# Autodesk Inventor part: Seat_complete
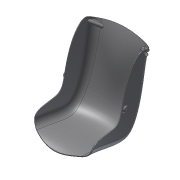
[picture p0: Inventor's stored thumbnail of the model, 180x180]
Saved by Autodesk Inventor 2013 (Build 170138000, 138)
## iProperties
Shininess: 64.0
Length Units: 11269
Angle Units: 11279
Time Units: 11290
Mass Units: 11283
Length Display Precision: 3
Angle Display Precision: 2
Compacted: True
Part Number: Seat_complete
Document SubType Name: Modeling
Created: 2002-10
Designer: FranzK
Density: 1 g/cm^3
Material: Generic
Density: 0.0
Volumn: 0.0
Area: 0.0
PropertySet Name: Model Information
Control State: 0
Master: False
Checked Out: False
Author: FranzK
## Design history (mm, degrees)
sketch "Sketch1"
  geometry: L1 (0, 40)-(0, 422.426) reference; L2 (0, 40)-(-230, 40); L3 (-230, 40)-(-230, 420); L4 (-230, 420)-(0, 420) reference; L5 (230, 40)-(230, 420); L6 (0, 40)-(230, 40); L7 (230, 420)-(0, 420)
  constraints: 14 end point, 2 symmetric about line, 2 vertical, 1 horizontal, 1 parallel, 1 perpendicular, 1 point on line, 3 other
  dimensions: "d0" = 460 diameter of L2.end L1; "d1" = 380 distance between parallel lines of L2 L4; "d2" = 90 deg angle of L2 L3
extrude "Extrusion1" new body sketch "Sketch1" distance "d3" = 600; taper "d4" = 0 deg
workplane "Work Plane2"
workplane "Work Plane3"
sketch "Sketch11"
  geometry: L1 (0, 380)-(-600, 380) reference; L2 (-600, 380)-(-600, 552.047); L3 (-600, 552.047)-(0, 380)
  constraints: 4 end point, 1 perpendicular
  dimensions: "d79" = 16 deg angle of L1 L3
extrude "Extrusion3" cut sketch "Sketch11" stored distance "d8" = 600; taper "d9" = 0 deg
sketch "Sketch2"
  geometry: L1 (600, -552.047)-(600, 0) reference; L2 (0, 0)-(600, 0) reference; L3 (0, 0)-(0, -380) reference; L4 (600, -340)-(40, 0); L5 (0, -380)-(600, -552.047) reference
  constraints: 2 end point, 2 point on line
extrude "Extrusion2" join sketch "Sketch2" stored distance "d80" = 10; taper "d81" = 0 deg
sketch "Sketch4"
  geometry: L1 (230, 592.047)-(230, 380) reference; L2 (-230, 592.047)-(-230, 380) reference; A1 r 600 centre (0, 57.881) between (230, 612.047) and (-230, 612.047)
  constraints: 2 point on circle, 2 point on line, 1 centre point, 1 horizontal alignment
  dimensions: "d43" = 600 radius of A1; "d82" = 20 distance of L1.start A1.start
sketch "Sketch3"
  geometry: A1 r 800 centre (230, 766.225) between (0, 0) and (460, 0)
  constraints: 2 point on circle, 1 centre point
  dimensions: "d42" = 800 radius of A1
sketch "Sketch5"
  geometry: A1 r 570 centre (230, 521.536) between (0, 0) and (460, 0)
  constraints: 2 point on circle, 1 centre point
  dimensions: "d71" = 570 radius of A1
sketch "Sketch8"
  geometry: 2 further points
loft "Loft1" dims "d83" = 0, "d84" = 90 deg, "d85" = 0, "d86" = 90 deg, "d87" = 0, "d88" = 90 deg, "d89" = 0, "d90" = 90 deg, "d91" = 0, "d92" = 90 deg, "d93" = 0, "d94" = 90 deg
feature "Replace Face5"
fillet "Fillet7" dims "d193" = 3.5
sketch "Sketch19"
  geometry: L1 (186.993, -31.806)-(188.18, -27.025); L2 (233.225, -43.278)-(234.435, -38.401); L3 (186.993, -31.806)-(200.75, -35.219); L4 (220.161, -40.036)-(233.225, -43.278); A1 r 10 centre (210.456, -37.628) between (220.161, -40.036) and (200.75, -35.219)
  constraints: 8 end point, 2 perpendicular, 2 point on circle, 1 centre point, 1 parallel, 1 other
  dimensions: "d224" = 20 diameter of A1
revolve "Revolution1" sketch "Sketch19" dims angle "d65" = 90 deg
split "Split1"
revolve "Revolution2" dims angle "d77" = 120 deg
split "Split2"
fillet "Fillet8" dims "d194" = 1
feature "Surface2"
feature "OffsetSrf3" dims "d159" = 2, "d160" = 2
feature "OffsetSrf4" dims "d172" = 5, "d173" = 20
sketch "Sketch15"
  geometry: 10 further points
  constraints: 9 other
extrude "Extrusion7" sketch "Sketch15" dims "d195" = 1596.5, "d196" = 0
chamfer "Chamfer1" distance "d210" = 1; stored, may be unused: second distance "d211" = 2, angle "d234" = 45 deg
chamfer "Chamfer2" distance "d213" = 1; stored, may be unused: second distance "d214" = 2, angle "d235" = 45 deg
body "Solid1"
workplane "Work Plane1"
workpoint "Work Point1"
workpoint "Work Point2"
workpoint "Work Point3"
workpoint "Work Point4"
workplane "Work Plane4"
sketch "Sketch7"
  geometry: 10 further points
  constraints: 3 coincident, 7 other
workplane "Work Plane5"
workpoint "Work Point5"
workpoint "Work Point6"
workplane "Work Plane6"
fillet "Fillet1" dims "d104" = 60
shell "Shell1" dims "d78" = 5
fillet "Fillet2" dims "d107" = 20
workaxis "Work Axis1"
workpoint "Work Point7"
workplane "Work Plane7"
workplane "Work Plane8"
sketch "Sketch12"
  geometry: L1 (0, 14.495)-(77, 14.495); L2 (77, 14.495)-(77, -14.495); L3 (77, -14.495)-(0, -14.495); L4 (0, -14.495)-(0, 14.495); 1 further point
  constraints: 8 end point, 2 horizontal, 2 parallel, 1 perpendicular, 1 vertical alignment, 1 other
extrude "Extrusion4" cut sketch "Sketch12" stored distance "d162" = 10; taper "d163" = 0 deg
sketch "Sketch13"
  geometry: L1 (0, 14.495)-(0, 12.995); L2 (0, -12.995)-(0, -14.495); A1 r 14.495 centre (0, 0) between (0, 14.495) and (0, -14.495); A2 r 12.995 centre (0, 0) between (0, 12.995) and (0, -12.995)
  constraints: 4 end point, 4 point on circle, 2 centre point, 2 vertical, 1 coincident, 1 concentric, 1 other
  dimensions: "d164" = 1.5 radial gap between concentric circles of A2 A1; "d189" = 14.495 radius of A1
extrude "Extrusion5" join sketch "Sketch13" distance "d165" = 200; taper "d166" = 0 deg
sketch "Sketch14"
  geometry: L1 (200, 0)-(200, 1.5) reference; L2 (0, 1.5)-(200, 1.5) reference; L3 (0, 1.5)-(0, 0) reference; L4 (0, 0)-(51.674, 0) reference; L5 (60.246, 0)-(51.674, 0) reference; L6 (60.246, 0)-(131.913, 0) reference; L7 (139.315, 0)-(131.913, 0) reference; L8 (139.315, 0)-(200, 0) reference; L9 (0, 27.49)-(200, 27.49) reference; L10 (200, 27.49)-(200, 28.99) reference; L11 (200, 27.49)-(200, 28.99) reference; L12 (126.744, 28.99)-(200, 28.99) reference; L13 (116.806, 28.99)-(126.744, 28.99) reference; L14 (67.443, 28.99)-(116.806, 28.99) reference; L15 (57.486, 28.99)-(67.443, 28.99) reference; L16 (0, 28.99)-(57.486, 28.99) reference; L17 (0, 28.99)-(0, 27.49) reference; L18 (0, 27.49)-(200, 27.49) reference
extrude "Extrusion6" join sketch "Sketch14" distance "d167" = 50; taper "d168" = 0 deg
fillet "Fillet3" dims "d169" = 8
fillet "Fillet4" dims "d170" = 20
mirror "Mirror1"
split "Split3"
fillet "Fillet5" dims "d190" = 3.5
fillet "Fillet6" dims "d192" = 1
split "Split4"
fillet "Fillet9" dims "d197" = 50
fillet "Fillet10" dims "d198" = 50
fillet "Fillet11" dims "d199" = 50
sketch "Sketch16"
  geometry: C1 r 17.5 at (335, -0.5); A1 r 17.5 centre (335, -0.5) between (331.936, 16.73) and (352.468, -1.554) reference
  constraints: 2 concentric, 1 centre point, 1 coincident
extrude "Extrusion8" join sketch "Sketch16" distance "d200" = 12.5; taper "d201" = 0 deg
fillet "Fillet12" dims "d202" = 12.5
sketch "Sketch17"
  geometry: C1 r 17.5 at (0, 0) reference
hole "Hole1" sketch "Sketch17" diameter "d203" = 8; stored, may be unused: countersink angle "d207" = 82 deg, drill point angle "d209" = 118 deg; dims "d204" = 6, "d205" = 4, "d206" = 2, "d208" = 20
mirror "Mirror2"
fillet "Fillet13" dims "d212" = 12.5
sketch "Sketch18"
  geometry: L1 (607.614, 485.18)-(597.941, 488.203); L2 (593.001, 438.42)-(585.254, 440.841); L3 (593.001, 438.42)-(596.581, 449.874); L4 (604.035, 473.726)-(607.614, 485.18); A1 r 12.495 centre (600.308, 461.8) between (604.035, 473.726) and (596.581, 449.874) reference
  constraints: 8 end point, 2 perpendicular, 2 point on circle, 1 centre point, 1 parallel, 2 other
extrude "Extrusion9" join sketch "Sketch18" stored distance "d218" = 40; taper "d219" = 0 deg
fillet "Fillet14" dims "d220" = 5
fillet "Fillet15" dims "d221" = 5
extrude "Extrusion10" join sketch "Sketch19" stored distance "d226" = 40; taper "d227" = 0 deg
sketch "Sketch20"
  geometry: C1 r 12.5 at (37.628, 210.456); A1 r 10 centre (37.628, 210.456) between (40.036, 220.161) and (35.219, 200.75) reference
  constraints: 1 centre point, 1 coincident, 1 concentric
  dimensions: "d228" = 25 diameter of C1
extrude "Extrusion11" cut sketch "Sketch20" stored distance "d229" = 604.75; taper "d230" = 0 deg
fillet "Fillet16" dims "d231" = 5
fillet "Fillet17" dims "d232" = 5
node "Projected Loop1"
sketch "Sketch6"
  geometry: L1 (1.491, 0)-(620.064, 0); L2 (151.491, 600)-(588.401, 600); A1 r 300 centre (415, 300) between (635.956, 502.925) and (194.044, 502.925); 2 further points
  constraints: 4 end point, 2 point on circle, 1 centre point, 1 horizontal, 1 horizontal alignment, 1 parallel, 1 point on line, 1 tangent
  dimensions: "d66" = 600 distance between parallel lines of L2 L1; "d67" = 300 radius of A1; "d73" = 5 horizontal distance of point (420, 0) A1.centre
body "Srf2"
sketch "Sketch9"
  geometry: 11 further points
  constraints: 3 coincident, 8 other
sketch "Sketch10"
  geometry: L1 (40, 0)-(40, 40) reference; L2 (440, 0)-(440, 40); A1 r 5639.188 centre (5679.188, 20) between (45.809, 275.888) and (45.809, -235.888); 1 further point
  constraints: 3 point on circle, 2 end point, 1 centre point, 1 midpoint, 1 vertical alignment
  dimensions: "d76" = 400 distance between parallel lines of L2 L1
body "Srf3"
body "Srf1"
body "Srf5"
node "Projected Loop3"
body "Srf6"
body "Srf7"
body "Srf4"
other parameters: "d7" = 0, "d10" = 0, "d44" = 90 deg, "d69" = 0, "d70" = 0, "d100" = 0, "d161" = -55
